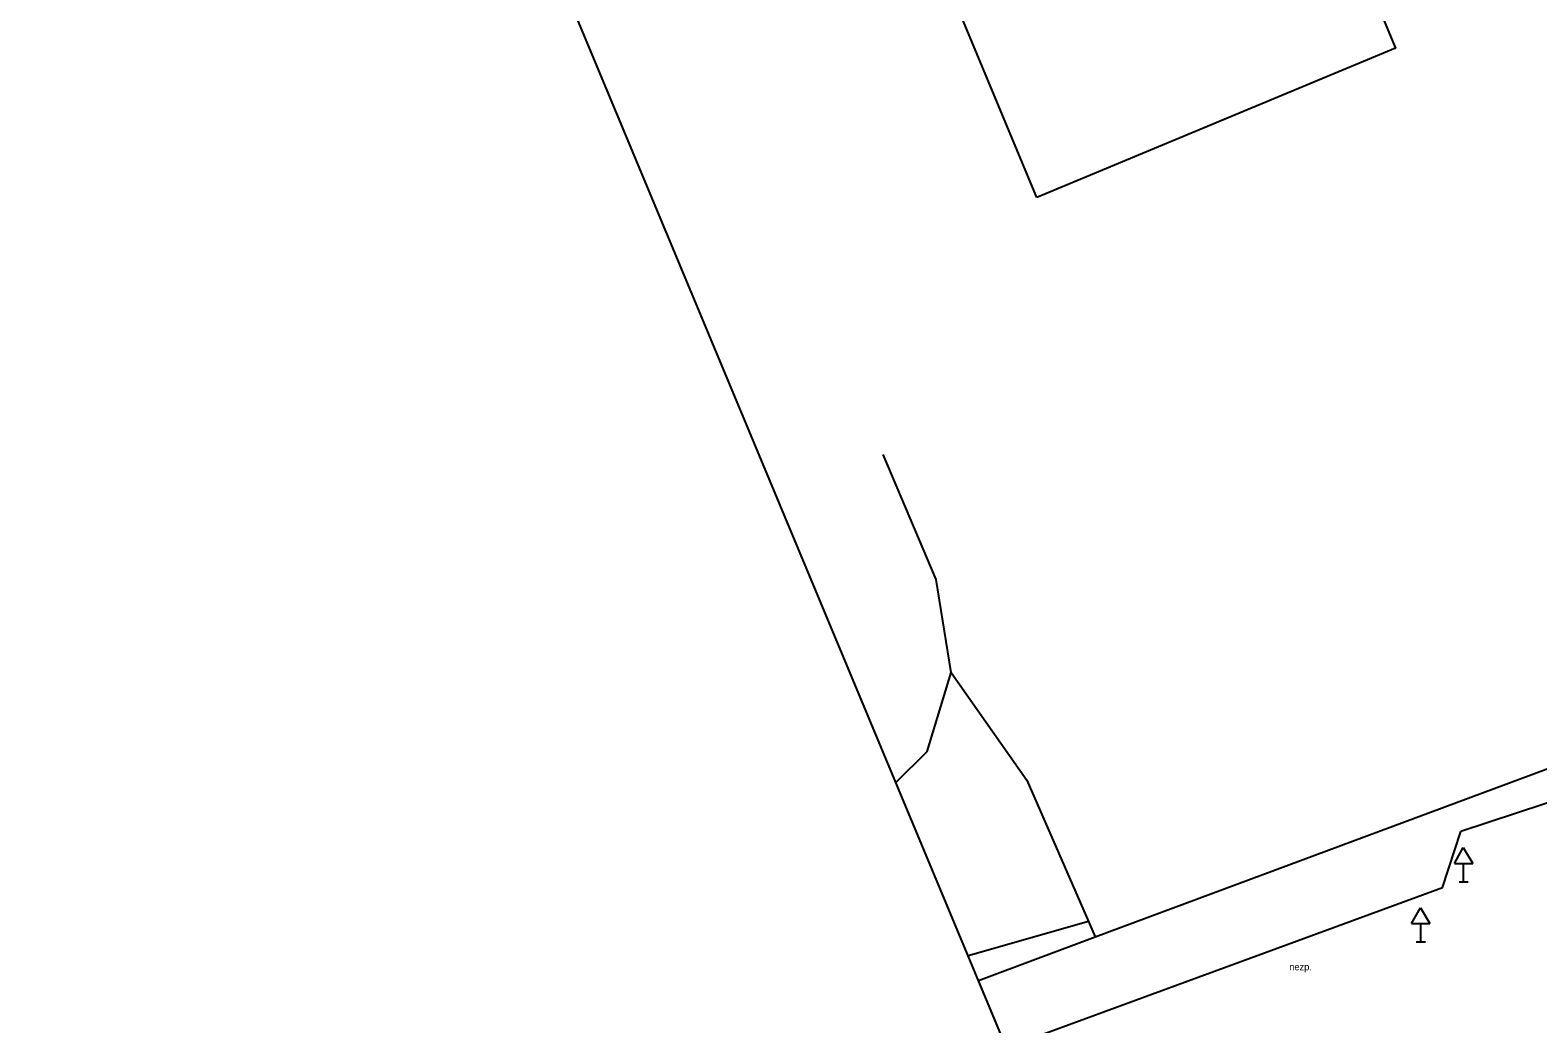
# Model space of a CAD drawing. Extents: x -834064 to -833847, y -1109181 to -1108930.
# Drawn here: x -834064.4 to -833982.9, y -1109112.7 to -1109058.9 of the extents above; entities that cross this region are included whole.
import ezdxf

# ---------------------------------------------------------------- set-up
doc = ezdxf.new("R2010")
doc.units = 0
for name, color, linetype in [('Doprava_body', 7, 'Continuous'), ('Hranice parcel', 7, 'Continuous'), ('OstPloch_popis', 7, 'Continuous'), ('Rozpiska_SŽ_netisknutelná', 7, 'Continuous'), ('Stavby_linie', 7, 'Continuous'), ('Vrstva 63', 7, 'Continuous')]:
    doc.layers.add(name, color=color, linetype=linetype)

msp = doc.modelspace()

# ---------------------------------------------------------------- linework, layer by layer
at = {"layer": 'Doprava_body'}
for p, q in [((-833987.42, -1109103.99), (-833986.939, -1109103.136)), ((-833986.939, -1109103.136), (-833986.42, -1109103.99)), ((-833987.42, -1109103.99), (-833986.42, -1109103.99)), ((-833986.92, -1109104.99), (-833986.92, -1109103.99)), ((-833987.17, -1109104.99), (-833986.67, -1109104.99)), ((-833989.74, -1109107.24), (-833989.259, -1109106.386)), ((-833989.259, -1109106.386), (-833988.74, -1109107.24)), ((-833989.74, -1109107.24), (-833988.74, -1109107.24)), ((-833989.24, -1109108.24), (-833989.24, -1109107.24)), ((-833989.49, -1109108.24), (-833988.99, -1109108.24))]:
    msp.add_line(p, q, dxfattribs=at)
at = {"layer": 'Hranice parcel'}
for p, q in [((-834006.84, -1109107.97), (-833970.57, -1109094.48)), ((-834006.84, -1109107.97), (-833970.57, -1109094.48)), ((-834007.2, -1109107.14), (-834006.84, -1109107.97)), ((-834007.2, -1109107.14), (-834006.84, -1109107.97))]:
    msp.add_line(p, q, dxfattribs=at)
for points in [[(-834014.62, -1109093.67), (-834015.42, -1109088.64), (-834018.283, -1109081.884)], [(-834014.62, -1109093.67), (-834015.42, -1109088.64), (-834018.283, -1109081.884)], [(-834017.609, -1109099.611), (-834015.91, -1109097.95), (-834014.62, -1109093.67)], [(-834017.609, -1109099.611), (-834015.91, -1109097.95), (-834014.62, -1109093.67)], [(-834014.62, -1109093.67), (-834010.52, -1109099.49), (-834007.2, -1109107.14)], [(-834014.62, -1109093.67), (-834010.52, -1109099.49), (-834007.2, -1109107.14)], [(-834007.2, -1109107.14), (-834013.701, -1109108.988)], [(-834007.2, -1109107.14), (-834013.701, -1109108.988)], [(-834013.148, -1109110.316), (-834006.84, -1109107.97)], [(-834013.148, -1109110.316), (-834006.84, -1109107.97)]]:
    msp.add_lwpolyline(points, dxfattribs=at)
at = {"layer": 'Rozpiska_SŽ_netisknutelná'}
msp.add_lwpolyline([(-834009.985, -1109067.995), (-834031.523, -1109016.312), (-834012.139, -1109008.234), (-833990.6, -1109059.916)], close=True, dxfattribs=at)
at = {"layer": 'Stavby_linie'}
for p, q in [((-833979.56, -1109099.8), (-833987.08, -1109102.26)), ((-833988.07, -1109105.29), (-833987.08, -1109102.26)), ((-834011.633, -1109113.951), (-833988.07, -1109105.29))]:
    msp.add_line(p, q, dxfattribs=at)
at = {"layer": 'Vrstva 63'}
msp.add_line((-833983.612, -1109181.188), (-834064.392, -1108987.352), dxfattribs=at)

# ---------------------------------------------------------------- texts
at = {"layer": 'OstPloch_popis'}
msp.add_text('nezp.', height=0.375, dxfattribs=at).set_placement((-833996.346, -1109109.771))

doc.saveas('drawing.dxf')
